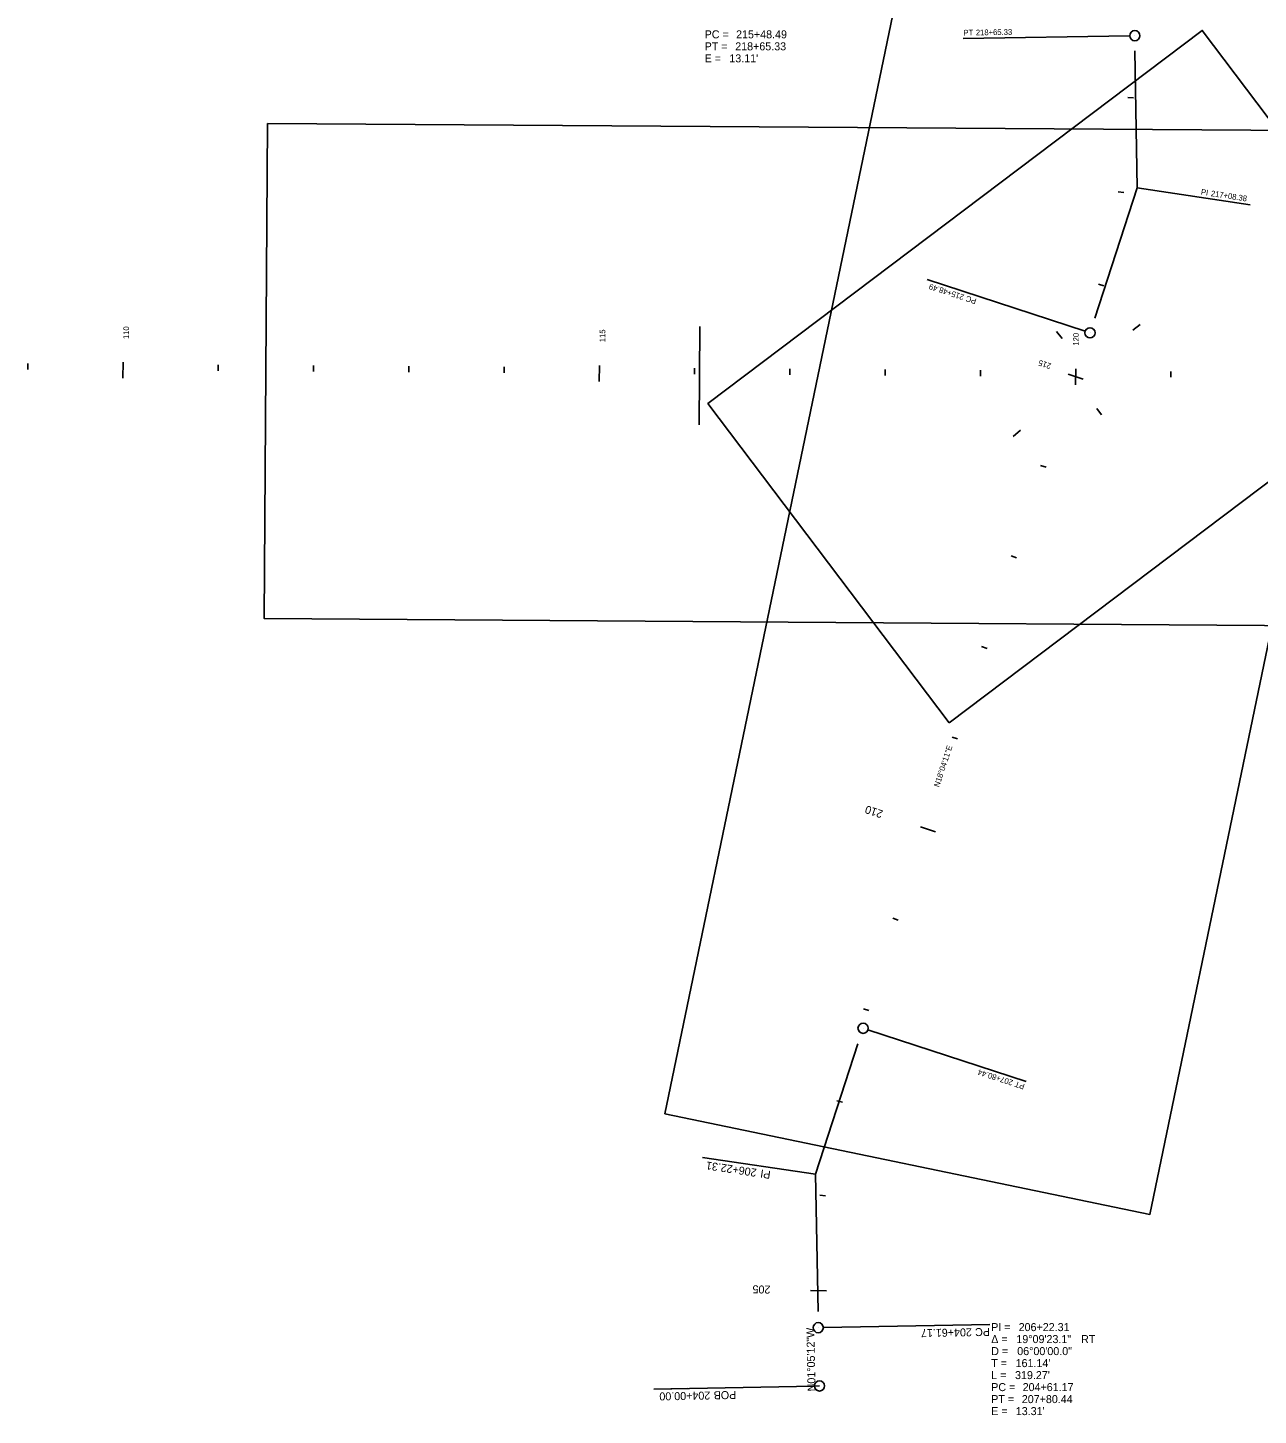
# Model space of a CAD drawing. Extents: x 1802372 to 1804572, y 572722 to 575010.
# Drawn here: x 1802372 to 1803664, y 572722 to 574179 of the extents above; entities that cross this region are included whole.
import ezdxf

# ---------------------------------------------------------------- set-up
doc = ezdxf.new("R2010")
doc.units = 0
for name, color, linetype in [('MOD_COR_Point Control', 7, 'Continuous'), ('MOD_COR_TemplateDrop', 7, 'Continuous'), ('MOD_Points', 7, 'Continuous')]:
    doc.layers.add(name, color=color, linetype=linetype)

msp = doc.modelspace()

# ---------------------------------------------------------------- linework, layer by layer
at = {"layer": 'MOD_COR_Point Control'}
for points in [[(1803040.9, 573038.4), (1803550, 572932.9), (1803871.5, 574483.7), (1803362.3, 574589.2)], [(1803339.3, 573448.9), (1803858.1, 573840.6), (1803605, 574175.8), (1803086.2, 573784.1)], [(1802624, 574078.2), (1802620.4, 573558.3), (1804220.3, 573547.1), (1804223.9, 574067.1)]]:
    msp.add_lwpolyline(points, close=True, dxfattribs=at)
at = {"layer": 'MOD_COR_TemplateDrop'}
for p, q in [((1803077.5, 573865.1), (1803076.8, 573761.7)), ((1803451.9, 573859.6), (1803458, 573852.3)), ((1803532.2, 573861), (1803539.9, 573867.2)), ((1803499.2, 573772.1), (1803494.3, 573779)), ((1803406.4, 573749.5), (1803414.2, 573756))]:
    msp.add_line(p, q, dxfattribs=at)
at = {"layer": 'MOD_Points'}
for p, q in [((1803528.8, 574170.2), (1803354.2, 574167.4)), ((1803354.2, 574167.4), (1803354.2, 574167.4)), ((1803534.2, 574170.3), (1803534.2, 574170.3)), ((1803536.8, 574010.5), (1803534.4, 574154.4)), ((1803527, 574105.3), (1803533, 574105)), ((1803536.8, 574010.5), (1803492.1, 573873.6)), ((1803516.7, 574006.5), (1803522.6, 574005.6)), ((1803536.8, 574010.5), (1803655.4, 573992.6)), ((1803655.4, 573992.6), (1803655.4, 573992.6)), ((1803482.1, 573860.1), (1803316.1, 573914.3)), ((1803316.1, 573914.3), (1803316.1, 573914.3)), ((1803496, 573909.4), (1803501.8, 573907.8)), ((1803487.2, 573858.4), (1803487.2, 573858.4)), ((1802372.2, 573826), (1802372.2, 573820)), ((1802472.2, 573827.7), (1802472.1, 573810.9)), ((1802572.2, 573824.6), (1802572.2, 573818.6)), ((1802672.2, 573823.9), (1802672.2, 573817.9)), ((1802772.2, 573823.2), (1802772.2, 573817.2)), ((1802872.2, 573822.5), (1802872.2, 573816.5)), ((1802972.2, 573824.2), (1802972.1, 573807.4)), ((1803072.2, 573821.1), (1803072.2, 573815.1)), ((1803172.2, 573820.4), (1803172.2, 573814.4)), ((1803272.2, 573819.7), (1803272.2, 573813.7)), ((1803372.2, 573819), (1803372.2, 573813)), ((1803472.2, 573820.7), (1803472.1, 573803.9)), ((1803572.2, 573817.7), (1803572.1, 573811.7)), ((1803464.2, 573815), (1803480.1, 573809.7)), ((1803435.4, 573719.1), (1803441.1, 573717.3)), ((1803404.4, 573624.1), (1803410.1, 573622.2)), ((1803373.4, 573529), (1803379.1, 573527.1)), ((1803342.4, 573433.9), (1803348.1, 573432.1)), ((1803309.1, 573339.6), (1803325, 573334.4)), ((1803280.3, 573243.8), (1803286, 573241.9)), ((1803249.3, 573148.7), (1803255, 573146.9)), ((1803249, 573128.3), (1803249, 573128.3)), ((1803254, 573126.6), (1803420.1, 573072.4)), ((1803199, 572975.1), (1803243.6, 573112)), ((1803420.1, 573072.4), (1803420.1, 573072.4)), ((1803221.4, 573052.2), (1803227.3, 573050.8)), ((1803199, 572975.1), (1803080.3, 572992.8)), ((1803080.3, 572992.8), (1803080.3, 572992.8)), ((1803199, 572975.1), (1803201.7, 572831.1)), ((1803203.5, 572953.2), (1803209.5, 572952.5)), ((1803193.7, 572853), (1803210.5, 572852.6)), ((1803202, 572814), (1803202, 572814)), ((1803207.4, 572814.1), (1803382, 572817.4)), ((1803382, 572817.4), (1803382, 572817.4)), ((1803197.9, 572752.7), (1803029.2, 572749.5)), ((1803197.2, 572752.7), (1803203.2, 572752.8)), ((1803203.2, 572752.8), (1803203.2, 572752.8)), ((1803029.2, 572749.5), (1803065.2, 572750.2))]:
    msp.add_line(p, q, dxfattribs=at)
for centre in [(1803534.2, 574170.3), (1803487.2, 573858.4), (1803249, 573128.3), (1803202, 572814), (1803203.2, 572752.8)]:
    msp.add_circle(centre, 5.34, dxfattribs=at)

# ---------------------------------------------------------------- texts
for s, p in [('PC = ', (1803082.7, 574167.5)), ('215+48.49', (1803115.7, 574167.5)), ('PT = ', (1803082.7, 574154.9)), ('E = ', (1803082.7, 574142.3)), ("13.11'", (1803108.6, 574142.3)), ('218+65.33', (1803114.8, 574154.9)), ('PI = ', (1803383.5, 572810.4)), ('206+22.31', (1803412.3, 572810.4)), ('Δ = ', (1803383.5, 572797.8)), ('19°09\'23.1"', (1803409.9, 572797.8)), (' RT', (1803474.7, 572797.8)), ('D = ', (1803383.5, 572785.2)), ('06°00\'00.0"', (1803410.8, 572785.2)), ('T = ', (1803383.5, 572772.6)), ('L = ', (1803383.5, 572760)), ("319.27'", (1803408.5, 572760)), ("161.14'", (1803409.1, 572772.6)), ('PC = ', (1803383.5, 572747.4)), ('204+61.17', (1803416.5, 572747.4)), ('PT = ', (1803383.5, 572734.8)), ('207+80.44', (1803415.6, 572734.8)), ('E = ', (1803383.5, 572722.2)), ("13.31'", (1803409.3, 572722.2))]:
    msp.add_text(s, height=8.4, dxfattribs=at).set_placement(p)
for s, height, rotation, p in [('PT', 6, 0.9408, (1803354.4, 574170.4)), ('218+65.33', 6, 0.9408, (1803367.4, 574170.6)), ('PI ', 6, 351.4356, (1803603.3, 574003.5)), ('217+08.38', 6, 351.4356, (1803613.8, 574001.9)), ('215+48.49', 6, 161.9303, (1803355.6, 573898.2)), ('PC', 6, 161.9303, (1803368.5, 573894)), ('110', 6, 89.6021, (1802478.4, 573851.8)), ('115', 6, 89.6021, (1802978.4, 573848.5)), ('120', 6, 89.6021, (1803475.4, 573844.9)), ('215', 6, 161.9303, (1803447, 573825.9)), ('N18°04\'11"E', 6, 71.9303, (1803328.8, 573380.9)), ('210', 8.4, 161.9303, (1803270.6, 573356.6)), ('207+80.44', 6, 161.9303, (1803406.9, 573073.6)), ('PT', 6, 161.9303, (1803419.2, 573069.6)), ('206+22.31', 8.4, 171.5085, (1803137.7, 572980.6)), ('PI ', 8.4, 171.5085, (1803152.4, 572978.4)), ('205', 8.4, 178.757, (1803151.8, 572858.1)), ('N01°05\'12"W', 8.4, 91.0867, (1803199.1, 572747.2)), ('204+61.17', 8.4, 181.0867, (1803363.1, 572813.4)), ('PC', 8.4, 181.0867, (1803382.1, 572813.8)), ('204+00.00', 8.4, 181.0867, (1803088.5, 572747)), ('POB ', 8.4, 181.0867, (1803115.8, 572747.6))]:
    msp.add_text(s, height=height, rotation=rotation, dxfattribs=at).set_placement(p)

doc.saveas('drawing.dxf')
